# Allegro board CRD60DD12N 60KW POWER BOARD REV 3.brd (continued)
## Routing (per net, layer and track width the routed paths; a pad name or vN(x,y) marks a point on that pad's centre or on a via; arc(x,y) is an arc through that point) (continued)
N13260: length 9.2
  BOTTOM w1.016: D24.1 191.68,11.38 190.63,10.33 D23.3 189.48,7.62 188.59,6.73 CT4.4
N13264: length 59.8
  TOP w2.54: 213.01,20.35 213.01,30.77 Q7.1 ; Q8.1 231.14,25.72 228.12,22.7 228.12,21.43 224.47,17.78 220.81,17.78
  TOP w3.81: 212.41,14.61 215.58,17.78 ; 215.58,17.78 220.81,17.78 ; 215.58,17.78 213.01,20.35
  TOP w7.62: 212.41,14.61 204.79,14.61 199.71,19.68 CT4.1
N13296: length 176.2
  TOP w7.62: 288.29,43.81 287.34,44.77 287.34,47.31 279.72,54.93 169.5,54.93 167.56,56.86 L4.1 167.06,56.1 167.06,39.73 187.1,19.68 CT4.2
N13300: length 5.8
  BOTTOM w1.016: C24.1 240.79,33.53 241.3,33.02 Q8.4 241.27,31.09 FB8.2
N13376: length 7.4
  BOTTOM w1.016: R9.1 238.44,28.68 238.44,28.89 238.76,29.21 238.76,29.31 ; 238.76,29.31 R28.2 ; 238.76,29.31 Q8.3 238.76,33.27 239.27,33.78 C24.2
N122921: length 2.3
  BOTTOM w1.016: R36.1 R35.2
N123081: length 2.3
  BOTTOM w1.016: R37.1 R36.2
N123401: length 2.3
  BOTTOM w1.016: R39.1 R38.2
N123561: length 2.3
  BOTTOM w1.016: R40.1 R39.2
N12042408: length 3.9
  BOTTOM w1.016: D19.1 193.42,117.22 194.5,116.14 ZD7.1
N12045153: length 3.9
  BOTTOM w1.016: ZD8.1 195.26,7.56 195.2,7.62 194.69,7.62 193.68,8.64 D23.1
N12047025: length 3.6
  BOTTOM w1.016: ZD5.1 194.94,239.97 194.08,240.83 193.63,240.83 193.42,241.05 D11.1
N12048829: length 3.7
  BOTTOM w1.016: D15.1 193.8,132.46 194.56,131.7 ZD6.1
N12055866: length 5.1
  TOP w1.016: R59.2 R60.1
N12061792: length 5.9
  BOTTOM w1.016: R41.2 R42.1
N12061794: length 5.2
  BOTTOM w1.016: R42.2 R43.1
N12062725: length 4.5
  BOTTOM w1.016: R44.2 R45.1
N12062727: length 3.9
  BOTTOM w1.016: R46.1 334.96,16.46 334.86,16.36 R45.2
N12099195: length 5.1
  TOP w1.016: R61.2 R12.1
N12120580: length 5
  TOP w1.016: R11.1 326.8,247.46 326.92,247.33 328.94,247.33 329.1,247.48 R64.2
N12122904: length 4.3
  BOTTOM w1.016: R17.2 R18.1
N12122941: length 4.3
  BOTTOM w1.016: R20.2 R21.1
N12122950: length 5.2
  BOTTOM w1.016: 299.03,243.71 304.22,243.71
N12123059: length 4.5
  BOTTOM w1.016: 290.14,243.71 294.69,243.71
N12123067: length 4.4
  BOTTOM w1.016: R14.2 R15.1

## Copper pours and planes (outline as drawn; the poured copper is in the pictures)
GND_SIGNAL on ART03: 269.88,125.09 269.88,113.67 340.04,113.67 340.04,125.09
G1H_RTN on ART03: 234.31,220.98 235.21,221.35 235.59,222.25 235.59,224.79 235.35,225.96 234.69,226.96 229.5,232.15 228.83,233.14 228.6,234.31 228.6,237.49 228.23,238.39 227.33,238.76 220.34,238.76 219.45,238.39 219.07,237.49 219.07,233.68 218.84,232.51 218.18,231.51 213.62,226.96 212.96,225.96 212.72,224.79 212.72,222.25 213.1,221.35 214,220.98 217.17,220.98 218.07,221.35 218.44,222.25 218.44,222.88 218.67,224.06 219.34,225.05 220.72,226.43 221.71,227.1 222.88,227.33 226.06,227.33 227.23,227.1 228.23,226.43 228.97,225.69 229.64,224.69 229.87,223.52 229.87,222.25 230.24,221.35 231.14,220.98
G1L_RTN on ART03: 220.34,152.4 219.45,152.03 219.07,151.13 219.07,148.59 219.31,147.42 219.97,146.42 221.99,144.41 222.65,143.41 222.88,142.24 222.88,133.35 223.26,132.45 224.16,132.08 231.14,132.08 232.04,132.45 232.41,133.35 232.41,140.97 232.78,141.87 233.68,142.24 235.59,142.24 236.76,142.47 237.75,143.14 241.04,146.42 241.7,147.42 241.94,148.59 241.94,151.13 241.56,152.03 240.66,152.4 237.49,152.4 236.59,152.03 236.22,151.13 236.22,150.5 235.99,149.32 235.32,148.33 233.94,146.95 232.95,146.28 231.78,146.05 228.6,146.05 227.43,146.28 226.43,146.95 225.69,147.69 225.02,148.69 224.79,149.86 224.79,151.13 224.42,152.03 223.52,152.4
G2H_RTN on ART03: 234.31,95.89 235.21,96.26 235.59,97.16 235.59,99.69 235.35,100.87 234.69,101.86 229.5,107.05 228.83,108.05 228.6,109.22 228.6,112.39 228.23,113.29 227.33,113.67 220.34,113.67 219.45,113.29 219.07,112.39 219.07,108.58 218.84,107.41 218.18,106.42 213.62,101.86 212.96,100.87 212.72,99.69 212.72,97.16 213.1,96.26 214,95.89 217.17,95.89 218.07,96.26 218.44,97.16 218.44,97.79 218.67,98.96 219.34,99.96 220.72,101.34 221.71,102 222.88,102.23 226.06,102.23 227.23,102 228.23,101.34 228.97,100.59 229.64,99.6 229.87,98.42 229.87,97.16 230.24,96.26 231.14,95.89
G2L_RTN on ART03: 220.34,27.94 219.45,27.57 219.07,26.67 219.07,24.13 219.31,22.96 219.97,21.96 221.99,19.95 222.65,18.95 222.88,17.78 222.88,8.26 223.26,7.36 224.16,6.99 231.14,6.99 232.04,7.36 232.41,8.26 232.41,16.51 232.78,17.41 233.68,17.78 235.59,17.78 236.76,18.01 237.75,18.68 241.04,21.96 241.7,22.96 241.94,24.13 241.94,26.67 241.56,27.57 240.66,27.94 237.49,27.94 236.59,27.57 236.22,26.67 236.22,26.04 235.99,24.86 235.32,23.87 233.94,22.49 232.95,21.82 231.78,21.59 228.6,21.59 227.43,21.82 226.43,22.49 225.69,23.23 225.02,24.23 224.79,25.4 224.79,26.67 224.42,27.57 223.52,27.94
PV_-VE on TOP: 377.86,28.96 378.54,29.95 378.78,31.11 378.72,99.11 378.95,100.29 379.61,101.28 390.46,112.13 391.46,112.8 392.63,113.03 397.19,113.03 398.09,112.66 398.46,111.76 398.46,4.13 398.09,3.23 397.19,2.86 370.9,2.86 370.01,3.23 369.63,4.13 369.63,19.75 369.87,20.92 370.55,21.9
PV_-VE on TOP: 43.18,71.44 43.55,70.54 44.45,70.17 73.98,70.17 74.88,70.54 75.25,71.44 75.25,177.8 74.88,178.7 73.98,179.07 44.45,179.07 43.55,178.7 43.18,177.8
PV_-VE on BOTTOM: outline of 87 points within 33.34,3.17 398.14,248.6 ; 6 cut-outs
PV_-VE on ART02: 2.22,246.38 2.22,3.81 398.46,3.81 398.46,246.38 ; 3 cut-outs
PV_-VE on ART03: 386.4,29.53 386.03,28.63 385.13,28.26 338.77,28.26 337.87,28.63 337.5,29.53 337.5,214.31 337.87,215.21 338.77,215.58 385.13,215.58 386.03,215.21 386.4,214.31
N00134 on TOP: 1.27,194.31 1.64,193.41 2.54,193.04 11.11,193.04 12.28,192.8 13.26,192.12 18.81,186.34 19.79,185.66 20.95,185.42 34.29,185.42 35.19,185.79 35.56,186.69 35.56,247.33 35.19,248.23 34.29,248.6 2.54,248.6 1.64,248.23 1.27,247.33
N00134 on BOTTOM: 1.27,212.72 1.64,211.83 2.54,211.46 22.54,211.46 23.44,211.83 23.81,212.72 23.81,247.33 23.44,248.23 22.54,248.6 2.54,248.6 1.64,248.23 1.27,247.33
N00143 on TOP: 1.27,170.81 1.64,171.71 2.54,172.09 10.79,172.09 11.97,172.32 12.96,172.98 19.42,179.44 20.42,180.11 21.59,180.34 34.29,180.34 35.19,179.97 35.56,179.07 35.56,128.27 35.19,127.37 34.29,127 2.54,127 1.64,127.37 1.27,128.27
N00143 on BOTTOM, ART02, ART03: 2.22,157.8 2.59,158.7 3.49,159.07 21.91,159.07 22.81,158.7 23.18,157.8 23.18,127.32 22.81,126.42 21.91,126.05 3.49,126.05 2.59,126.42 2.22,127.32
N00161 on BOTTOM, ART02, ART03: 2.54,168.91 1.64,169.28 1.27,170.18 1.27,199.71 1.64,200.61 2.54,200.98 16.19,200.98 17.09,200.61 17.46,199.71 17.46,170.18 17.09,169.28 16.19,168.91
N00267 on ART02: 60.71,162.43 60.71,179.2 60.95,179.44 61.95,180.11 63.12,180.34 66.67,180.34 67.85,180.57 68.84,181.24 69.59,181.98 70.58,182.65 71.75,182.88 85.72,182.88 86.9,182.65 87.89,181.98 88.64,181.24 89.3,180.24 89.53,179.07 89.53,163.83 89.3,162.66 88.64,161.66 87.26,160.28 86.26,159.62 85.09,159.38 71.75,159.38 70.58,159.62 69.59,160.28 68.71,161.16 63.25,161.16 62.07,161.4 61.08,162.06
N03399 on TOP: 270.51,202.87 269.61,203.24 269.24,204.14 269.24,217.81 269.61,218.7 270.51,219.07 271.14,219.07 272.04,218.7 272.42,217.81 272.42,211.77 272.79,210.87 273.69,210.5 278.76,210.5 279.66,210.87 280.04,211.77 280.04,217.49 280.41,218.39 281.31,218.76 281.94,218.76 282.84,218.39 283.21,217.49 283.21,211.77 283.58,210.87 284.48,210.5 288.29,210.5 289.19,210.87 289.56,211.77 289.56,217.17 289.93,218.07 290.83,218.44 291.46,218.44 292.36,218.07 292.74,217.17 292.74,211.77 293.11,210.87 294,210.5 299.08,210.5 299.98,210.87 300.36,211.77 300.36,217.81 300.73,218.7 301.62,219.07 302.26,219.07 303.16,218.7 303.53,217.81 303.53,204.17 303.16,203.27 302.26,202.9
N05349 on TOP: outline of 201 points within 274.32,3.17 398.46,248.6 ; 1 cut-out
N05349 on BOTTOM: 393.06,130.18 391.89,130.41 390.9,131.07 383.8,138.17 383.14,139.16 382.9,140.34 382.9,208.91 382.67,210.09 382.01,211.08 366.09,227 366.49,228.89 365.76,230.68 365.76,247.33 366.13,248.23 367.03,248.6 397.19,248.6 398.09,248.23 398.46,247.33 398.46,131.44 398.09,130.55 397.19,130.18
N08663 on TOP: 302.26,170.52 303.16,170.14 303.53,169.25 303.53,155.89 303.16,154.99 302.26,154.62 301.94,154.62 301.04,154.99 300.67,155.89 300.67,161.38 300.3,162.27 299.4,162.65 293.69,162.65 292.79,162.27 292.42,161.38 292.42,155.89 292.05,154.99 291.15,154.62 290.25,154.99 289.88,155.89 289.88,161.38 289.51,162.27 288.61,162.65 284.16,162.65 283.26,162.27 282.89,161.38 282.89,155.98 282.52,155.08 281.62,154.71 280.72,155.08 280.35,155.98 280.35,161.38 279.98,162.27 279.08,162.65 273.37,162.65 272.47,162.27 272.1,161.38 272.1,155.89 271.73,154.99 270.83,154.62 270.51,154.62 269.61,154.99 269.24,155.89 269.24,169.21 269.61,170.11 270.51,170.48
N12168 on TOP: 1.27,53.98 1.64,54.87 2.54,55.24 10.79,55.24 11.97,55.48 12.96,56.14 19.42,62.6 20.42,63.27 21.59,63.5 34.29,63.5 35.19,63.13 35.56,62.23 35.56,2.86 35.19,1.96 34.29,1.59 2.54,1.59 1.64,1.96 1.27,2.86
N12168 on BOTTOM: 22.54,38.1 23.44,37.73 23.81,36.83 23.81,2.86 23.44,1.96 22.54,1.59 2.54,1.59 1.64,1.96 1.27,2.86 1.27,36.83 1.64,37.73 2.54,38.1
N12176 on TOP: 2.54,121.28 1.64,120.91 1.27,120.02 1.27,77.47 1.64,76.57 2.54,76.2 11.43,76.2 12.6,75.97 13.6,75.3 19.42,69.48 20.42,68.81 21.59,68.58 34.29,68.58 35.19,68.95 35.56,69.85 35.56,120.02 35.19,120.91 34.29,121.28
N12176 on BOTTOM, ART02, ART03: 1.27,120.02 1.64,120.91 2.54,121.28 22.54,121.28 23.44,120.91 23.81,120.02 23.81,86.04 23.44,85.14 22.54,84.77 2.54,84.77 1.64,85.14 1.27,86.04
N12212 on BOTTOM, ART02, ART03: 3.17,47.5 2.28,47.87 1.91,48.77 1.91,77.47 2.28,78.37 3.17,78.74 15.88,78.74 16.77,78.37 17.14,77.47 17.14,48.77 16.77,47.87 15.88,47.5
N12260 on ART02: 60.71,72.52 60.71,88.65 62.36,90.3 68.07,90.3 70.48,92.71 86.36,92.71 89.22,89.85 89.22,71.44 86.36,68.58 71.12,68.58 68.58,71.12 62.1,71.12
N12748 on TOP: 270.57,77.97 269.67,78.34 269.3,79.23 269.3,92.9 269.67,93.8 270.57,94.17 271.2,94.17 272.1,93.8 272.47,92.9 272.47,86.87 272.85,85.97 273.74,85.6 278.82,85.6 279.72,85.97 280.09,86.87 280.09,92.59 280.47,93.48 281.36,93.86 282,93.86 282.9,93.48 283.27,92.59 283.27,86.87 283.64,85.97 284.54,85.6 288.35,85.6 289.25,85.97 289.62,86.87 289.62,92.27 289.99,93.17 290.89,93.54 291.52,93.54 292.42,93.17 292.79,92.27 292.79,86.87 293.17,85.97 294.06,85.6 299.14,85.6 300.04,85.97 300.41,86.87 300.41,92.9 300.79,93.8 301.68,94.17 302.32,94.17 303.22,93.8 303.59,92.9 303.59,79.27 303.22,78.37 302.32,78
N13296 on TOP: 302.18,46.51 303.07,46.14 303.45,45.24 303.45,31.34 303.07,30.44 302.18,30.07 301.54,30.07 300.64,30.44 300.27,31.34 300.27,37.37 299.9,38.27 299,38.64 293.92,38.64 293.02,38.27 292.65,37.37 292.65,31.66 292.28,30.76 291.38,30.39 290.75,30.39 289.85,30.76 289.48,31.66 289.48,37.37 289.1,38.27 288.21,38.64 284.4,38.64 283.5,38.27 283.13,37.37 283.13,31.97 282.75,31.08 281.86,30.7 281.22,30.7 280.32,31.08 279.95,31.97 279.95,37.37 279.58,38.27 278.68,38.64 273.6,38.64 272.7,38.27 272.33,37.37 272.33,31.34 271.96,30.44 271.06,30.07 270.43,30.07 269.53,30.44 269.16,31.34 269.16,45.21 269.53,46.11 270.43,46.48

Small or netless copper shapes (teardrops, artwork), in the pictures only: 3 on TOP, 3 on BOTTOM

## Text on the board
Ref Des/Silkscreen Top: CON14 | CON15 | CON16 | CON20 | CON12 | CON13 | CON10 | CON11 | rev3 | P/N: CRD60DD12P | 60kW 4 Channel Interleaved Boost Converter | OUTPUT | IN2 | IN1
XSECTION_CHART: *  SURFACE - AIR | L1: TOP CONDUCTOR - COPPER | *  DIELECTRIC - FR-4 | L2: ART02 CONDUCTOR - COPPER | L3: ART03 CONDUCTOR - COPPER | L4: BOTTOM CONDUCTOR - COPPER | DESIGN CROSS SECTION CHART | ___________________________ | TOTAL THICKNESS 94.2 MIL | 1-4
PAGE_OUTLINE: D | 1=1 | 3 | 3028 E. Cornwallis Rd. | Research Triangle Park, NC 27709 | 60kW Boost Power Board | CRD60DD12N_MAIN | 1 of 1
User.9: FIGURE | SIZE | 16.0 | 40.0 | 41.0 | 48.0 | 58.0 | 69.0 | 70.0 | 150.0 | 250.0 | 260.0 | 178.0 | 260.0x173.0 | 400.0x50.0 | DRILL CHART: TOP to BOTTOM | ALL UNITS ARE IN MILS | PLATED | NON-PLATED | QTY | 710 | 16 | 58 | 8 | 76 | 6 | 25
